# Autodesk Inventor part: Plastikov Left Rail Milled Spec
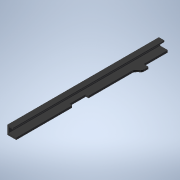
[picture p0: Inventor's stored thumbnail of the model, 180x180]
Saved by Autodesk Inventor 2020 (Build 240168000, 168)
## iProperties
Created: 2020-05
Part Number: Plastikov Left Rail Milled Spec
Material: Generic
Document SubType Name: Modeling
Designer: Iv. Tr.
Density: 1 g/cm^3
Appearance: Default
Title: D:\Downloads\Plastikov-v1-3\STEP\Plastikov Left Rail Milled Spec.stp
Author: johne
Sending System: Autodesk Inventor 2020
Preprocessor: ST-DEVELOPER v18
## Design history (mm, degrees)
feature "Solid1"
body "Solid2"
